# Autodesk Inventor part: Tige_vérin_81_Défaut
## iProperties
Shininess: 64.0
Length Units: 11269
Angle Units: 11279
Time Units: 11290
Mass Units: 11283
Length Display Precision: 3
Angle Display Precision: 2
Compacted: True
Part Number: Tige_vérin_81_Défaut
Document SubType Name: Modeling
Created: 2006-01
Material: Par défaut
Designer: riri
Density: 0.0
Volumn: 0.0
Area: 0.0
PropertySet Name: Model Information
Control State: 0
Master: False
Checked Out: False
Author: riri
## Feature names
1. Base1
